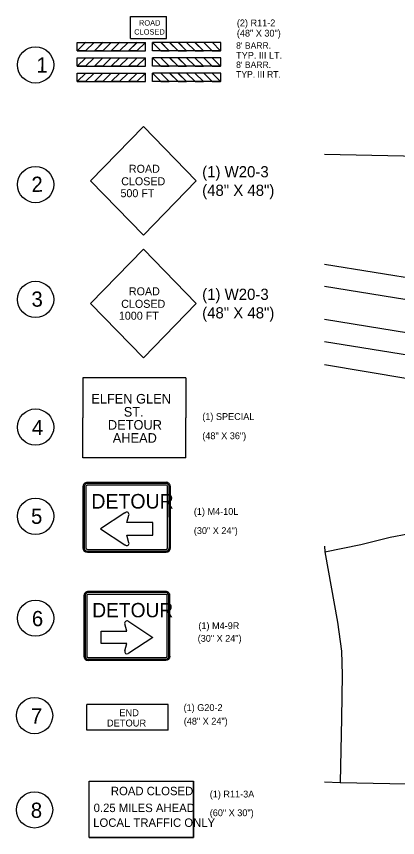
# Model space of a CAD drawing. Extents: x 185625 to 193575, y 1257500 to 1262681.
# Drawn here: x 185625 to 187128, y 1259342 to 1262581 of the extents above; entities that cross this region are included whole.
import ezdxf

# ---------------------------------------------------------------- set-up
doc = ezdxf.new("R2010")
doc.units = 0
for name, color, linetype in [('1', 7, 'Continuous'), ('10', 7, 'Continuous'), ('3', 7, 'Continuous'), ('8', 7, 'Continuous'), ('Level 42', 7, 'Continuous'), ('Level 8', 7, 'Continuous'), ('P_TC_Signs_Temporary', 7, 'Continuous')]:
    doc.layers.add(name, color=color, linetype=linetype)

msp = doc.modelspace()

# ---------------------------------------------------------------- linework, layer by layer
at = {"layer": '1'}
for p, q in [((185864.9, 1262445.4), (185898.6, 1262479.2)), ((185931.4, 1262479), (185897.9, 1262445.4)), ((185932.8, 1262445.4), (185966.6, 1262479.2)), ((185999.4, 1262479), (185965.8, 1262445.4)), ((185999.5, 1262445.4), (186033.2, 1262479.2)), ((186066, 1262479), (186032.5, 1262445.4)), ((186067.4, 1262445.4), (186101.1, 1262479.2)), ((186133.9, 1262479), (186100.4, 1262445.4)), ((186161.8, 1262479), (186195.3, 1262445.4)), ((186228.3, 1262445.4), (186194.6, 1262479.2)), ((186229.7, 1262479), (186263.3, 1262445.4)), ((186296.3, 1262445.4), (186262.6, 1262479.2)), ((186296.4, 1262479), (186329.9, 1262445.4)), ((186362.9, 1262445.4), (186329.2, 1262479.2)), ((186364.3, 1262479), (186397.8, 1262445.4)), ((186430.8, 1262445.4), (186397.1, 1262479.2)), ((185897.9, 1262445.4), (185864.9, 1262445.4)), ((185965.8, 1262445.4), (185932.8, 1262445.4)), ((186032.5, 1262445.4), (185999.5, 1262445.4)), ((186100.4, 1262445.4), (186067.4, 1262445.4)), ((186195.3, 1262445.4), (186228.3, 1262445.4)), ((186263.3, 1262445.4), (186296.3, 1262445.4)), ((186329.9, 1262445.4), (186362.9, 1262445.4)), ((186397.8, 1262445.4), (186430.8, 1262445.4)), ((185864.9, 1262384.8), (185898.6, 1262418.6)), ((185931.4, 1262418.4), (185897.9, 1262384.8)), ((185932.8, 1262384.8), (185966.6, 1262418.6)), ((185999.4, 1262418.4), (185965.8, 1262384.8)), ((185999.5, 1262384.8), (186033.2, 1262418.6)), ((186066, 1262418.4), (186032.5, 1262384.8)), ((186067.4, 1262384.8), (186101.1, 1262418.6)), ((186133.9, 1262418.4), (186100.4, 1262384.8)), ((186161.8, 1262418.4), (186195.3, 1262384.8)), ((186228.3, 1262384.8), (186194.6, 1262418.6)), ((186229.7, 1262418.4), (186263.3, 1262384.8)), ((186296.3, 1262384.8), (186262.6, 1262418.6)), ((186296.4, 1262418.4), (186329.9, 1262384.8)), ((186362.9, 1262384.8), (186329.2, 1262418.6)), ((186364.3, 1262418.4), (186397.8, 1262384.8)), ((186430.8, 1262384.8), (186397.1, 1262418.6)), ((185897.9, 1262384.8), (185864.9, 1262384.8)), ((185965.8, 1262384.8), (185932.8, 1262384.8)), ((186032.5, 1262384.8), (185999.5, 1262384.8)), ((186100.4, 1262384.8), (186067.4, 1262384.8)), ((186195.3, 1262384.8), (186228.3, 1262384.8)), ((186263.3, 1262384.8), (186296.3, 1262384.8)), ((186329.9, 1262384.8), (186362.9, 1262384.8)), ((186397.8, 1262384.8), (186430.8, 1262384.8)), ((185864.9, 1262324.2), (185898.6, 1262358)), ((185931.4, 1262357.8), (185897.9, 1262324.2)), ((185932.8, 1262324.2), (185966.6, 1262358)), ((185999.4, 1262357.8), (185965.8, 1262324.2)), ((185999.5, 1262324.2), (186033.2, 1262358)), ((186066, 1262357.8), (186032.5, 1262324.2)), ((186067.4, 1262324.2), (186101.1, 1262358)), ((186133.9, 1262357.8), (186100.4, 1262324.2)), ((186161.8, 1262357.8), (186195.3, 1262324.2)), ((186228.3, 1262324.2), (186194.6, 1262358)), ((186229.7, 1262357.8), (186263.3, 1262324.2)), ((186296.3, 1262324.2), (186262.6, 1262358)), ((186296.4, 1262357.8), (186329.9, 1262324.2)), ((186362.9, 1262324.2), (186329.2, 1262358)), ((186364.3, 1262357.8), (186397.8, 1262324.2)), ((186430.8, 1262324.2), (186397.1, 1262358)), ((185897.9, 1262324.2), (185864.9, 1262324.2)), ((185965.8, 1262324.2), (185932.8, 1262324.2)), ((186032.5, 1262324.2), (185999.5, 1262324.2)), ((186100.4, 1262324.2), (186067.4, 1262324.2)), ((186195.3, 1262324.2), (186228.3, 1262324.2)), ((186263.3, 1262324.2), (186296.3, 1262324.2)), ((186329.9, 1262324.2), (186362.9, 1262324.2)), ((186397.8, 1262324.2), (186430.8, 1262324.2)), ((186293, 1261155.8), (185887.4, 1261155.8)), ((185887.4, 1261155.8), (185887.4, 1260998.2)), ((186293, 1261155.8), (186293, 1260998.2)), ((185887.4, 1260840.5), (185887.4, 1260998.2)), ((186293, 1260840.5), (186293, 1260998.2)), ((186293, 1260840.5), (185887.4, 1260840.5))]:
    msp.add_line(p, q, dxfattribs=at)
msp.add_lwpolyline([(185912.2, 1259565.1), (186323.9, 1259565.1), (186323.9, 1259342.4), (185912.2, 1259342.4)], close=True, dxfattribs=at)
at = {"layer": '10'}
for points in [[(186840.7, 1262038.4), (188150.6, 1262010.8)], [(193575.5, 1260557.6), (193212.7, 1260596.5), (192742.7, 1260653.6), (192330.9, 1260716.5), (191888.1, 1260787.1), (191307.8, 1260876.8), (190478.8, 1261007.5), (190038.6, 1261084.8), (189048.5, 1261248.2), (187820.3, 1261444.8), (186840.7, 1261603.3)], [(186840.7, 1261517.2), (187806.8, 1261360.9), (189034.8, 1261164.3), (190024.3, 1261001), (190464.9, 1260923.6), (191294.7, 1260792.9), (191874.9, 1260703.1), (192317.8, 1260632.5), (192731.2, 1260569.4), (193203.1, 1260512.1), (193575.5, 1260472.1)], [(193575.5, 1260341.4), (193188.3, 1260382.9), (192713.5, 1260440.6), (192297.7, 1260504), (191854.7, 1260574.7), (191274.6, 1260664.4), (190443.5, 1260795.4), (190002.5, 1260872.9), (189014, 1261035.9), (187786.1, 1261232.6), (186840.7, 1261385.5)], [(186840.7, 1261299.4), (187772.6, 1261148.7), (189000.3, 1260952), (189988.2, 1260789.1), (190429.5, 1260711.5), (191261.5, 1260580.4), (191841.6, 1260490.7), (192284.6, 1260420), (192702, 1260356.4), (193178.6, 1260298.5), (193575.5, 1260255.9)], [(191582.4, 1259981.2), (191550.8, 1259987.2), (191524.3, 1260006.5), (191500.2, 1260059.6), (191471.2, 1260173), (191442.3, 1260243), (191410.9, 1260284), (191348.2, 1260337.1), (191275.8, 1260382.9), (191155.2, 1260424), (190983.1, 1260495.9), (190840.8, 1260546.5), (190511.6, 1260605.2), (189655.3, 1260749.8), (189036.5, 1260848.7), (188221.1, 1260983.9), (187505.6, 1261095.4), (186840.7, 1261207.7)], [(186840.7, 1260469.2), (186841.7, 1260469.4), (186983.7, 1260498.7), (187099, 1260527.9), (187168.8, 1260540.9)], [(186840.7, 1260491.3), (186841.7, 1260469.4), (186892.1, 1260192.5), (186906.7, 1260077.1), (186909.9, 1259984.5), (186906.7, 1259813.9), (186902, 1259559.2)], [(186840.7, 1259561.8), (186902, 1259559.2), (187228.5, 1259552.7), (187288.6, 1259565.3), (187338.9, 1259584.8), (187405.5, 1259610.8), (187459.1, 1259625.4), (187493.2, 1259631.9), (187552.1, 1259638.3), (187878.6, 1259630.2)]]:
    msp.add_lwpolyline(points, dxfattribs=at)
at = {"layer": '3'}
for p, q in [((186075.4, 1262493.8), (186075.4, 1262581.3)), ((186075.4, 1262581.3), (186217.6, 1262581.3)), ((186217.6, 1262493.8), (186217.6, 1262581.3)), ((185864.8, 1262479.1), (186134.1, 1262479.1)), ((185864.8, 1262445.3), (185864.8, 1262479.1)), ((185932.8, 1262445.4), (185966.4, 1262479)), ((185965.7, 1262445.4), (185999.5, 1262479.1)), ((185999.5, 1262445.4), (186033.3, 1262479.2)), ((186032.4, 1262445.3), (186066.1, 1262479)), ((186067.4, 1262445.4), (186101, 1262479)), ((186075.4, 1262493.8), (186217.6, 1262493.8)), ((186100.4, 1262445.4), (186134.1, 1262479.1)), ((186134.1, 1262445.3), (186134.1, 1262479.1)), ((186195.3, 1262445.4), (186161.6, 1262479.1)), ((186430.9, 1262479.1), (186161.6, 1262479.1)), ((186161.6, 1262445.3), (186161.6, 1262479.1)), ((186228.3, 1262445.4), (186194.7, 1262479)), ((186263.4, 1262445.3), (186229.6, 1262479)), ((186296.3, 1262445.4), (186262.5, 1262479.2)), ((186330, 1262445.4), (186296.3, 1262479.1)), ((186362.9, 1262445.4), (186329.4, 1262479)), ((186430.9, 1262445.3), (186430.9, 1262479.1)), ((185864.8, 1262445.3), (186134.1, 1262445.3)), ((186133.9, 1262445.4), (186134.1, 1262445.6)), ((186161.8, 1262445.4), (186161.6, 1262445.6)), ((186430.9, 1262445.3), (186161.6, 1262445.3)), ((185864.8, 1262418.5), (186134.1, 1262418.5)), ((185864.8, 1262384.7), (185864.8, 1262418.5)), ((185932.8, 1262384.8), (185966.4, 1262418.4)), ((185965.7, 1262384.8), (185999.5, 1262418.5)), ((185999.5, 1262384.8), (186033.3, 1262418.6)), ((186032.4, 1262384.7), (186066.1, 1262418.4)), ((186067.4, 1262384.8), (186101, 1262418.4)), ((186100.4, 1262384.8), (186134.1, 1262418.5)), ((186134.1, 1262384.7), (186134.1, 1262418.5)), ((186195.3, 1262384.8), (186161.6, 1262418.5)), ((186430.9, 1262418.5), (186161.6, 1262418.5)), ((186161.6, 1262384.7), (186161.6, 1262418.5)), ((186228.3, 1262384.8), (186194.7, 1262418.4)), ((186263.4, 1262384.7), (186229.6, 1262418.4)), ((186296.3, 1262384.8), (186262.5, 1262418.6)), ((186330, 1262384.8), (186296.3, 1262418.5)), ((186362.9, 1262384.8), (186329.4, 1262418.4)), ((186430.9, 1262384.7), (186430.9, 1262418.5)), ((185864.8, 1262384.7), (186134.1, 1262384.7)), ((186133.9, 1262384.8), (186134.1, 1262385)), ((186161.8, 1262384.8), (186161.6, 1262385)), ((186430.9, 1262384.7), (186161.6, 1262384.7)), ((185864.8, 1262357.9), (186134.1, 1262357.9)), ((185864.8, 1262324.1), (185864.8, 1262357.9)), ((185932.8, 1262324.2), (185966.4, 1262357.8)), ((185965.7, 1262324.2), (185999.5, 1262357.9)), ((185999.5, 1262324.2), (186033.3, 1262358)), ((186032.4, 1262324.1), (186066.1, 1262357.8)), ((186067.4, 1262324.2), (186101, 1262357.8)), ((186100.4, 1262324.2), (186134.1, 1262357.9)), ((186134.1, 1262324.1), (186134.1, 1262357.9)), ((186195.3, 1262324.2), (186161.6, 1262357.9)), ((186430.9, 1262357.9), (186161.6, 1262357.9)), ((186161.6, 1262324.1), (186161.6, 1262357.9)), ((186228.3, 1262324.2), (186194.7, 1262357.8)), ((186263.4, 1262324.1), (186229.6, 1262357.8)), ((186296.3, 1262324.2), (186262.5, 1262358)), ((186330, 1262324.2), (186296.3, 1262357.9)), ((186362.9, 1262324.2), (186329.4, 1262357.8)), ((186430.9, 1262324.1), (186430.9, 1262357.9)), ((185864.8, 1262324.1), (186134.1, 1262324.1)), ((186133.9, 1262324.2), (186134.1, 1262324.4)), ((186161.8, 1262324.2), (186161.6, 1262324.4)), ((186430.9, 1262324.1), (186161.6, 1262324.1)), ((185912.2, 1259565.1), (186323.9, 1259565.1)), ((185912.2, 1259342.4), (185912.2, 1259565.1)), ((186323.9, 1259342.4), (186323.9, 1259565.1)), ((185912.2, 1259342.4), (186323.9, 1259342.4))]:
    msp.add_line(p, q, dxfattribs=at)
at = {"layer": 'Level 42'}
for p, q in [((186224, 1259867.2), (185902.4, 1259867.2)), ((185902.4, 1259766.2), (185902.4, 1259867.2)), ((186224, 1259766.2), (186224, 1259867.2)), ((186224, 1259766.2), (185902.4, 1259766.2))]:
    msp.add_line(p, q, dxfattribs=at)
at = {"layer": 'Level 8'}
for p, q in [((186125.9, 1262146.9), (185917.5, 1261932.5)), ((186334.3, 1261932.5), (186125.9, 1262146.9)), ((186125.9, 1261718.4), (185917.5, 1261932.5)), ((186334.3, 1261932.5), (186125.9, 1261718.4)), ((186125.9, 1261663.5), (185917.5, 1261449.2)), ((186334.3, 1261449.2), (186125.9, 1261663.5)), ((186125.9, 1261235), (185917.5, 1261449.2)), ((186334.3, 1261449.2), (186125.9, 1261235))]:
    msp.add_line(p, q, dxfattribs=at)
for centre in [(185700.9, 1262389.9), (185701, 1261917.9), (185701, 1261465.2), (185701, 1260961.6), (185701, 1260609.6), (185701, 1260207.9), (185696.9, 1259823.6), (185696.8, 1259451.7)]:
    msp.add_circle(centre, 71.5, dxfattribs=at)
at = {"layer": 'P_TC_Signs_Temporary'}
for p, q in [((185887.7, 1260726.3), (185887.8, 1260484.9)), ((185892, 1260726.4), (185892.1, 1260484.9)), ((185899.2, 1260726.4), (185899.3, 1260484.9)), ((186215.3, 1260743.7), (185904.9, 1260743.6)), ((186215.3, 1260739.4), (185904.9, 1260739.3)), ((186215.3, 1260732.2), (185904.9, 1260732.1)), ((186221.2, 1260485.1), (186221.1, 1260726.5)), ((186228.4, 1260485.1), (186228.3, 1260726.5)), ((186232.7, 1260485.1), (186232.6, 1260726.5)), ((185905, 1260479.2), (186215.4, 1260479.3)), ((185905, 1260472), (186215.4, 1260472.1)), ((185905, 1260467.7), (186215.4, 1260467.8)), ((186214, 1260313.1), (185908.6, 1260313)), ((186214, 1260308.9), (185908.6, 1260308.7)), ((185891.6, 1260296), (185891.7, 1260058.5)), ((185895.9, 1260296), (185896, 1260058.5)), ((185902.9, 1260296), (185903, 1260058.5)), ((186214, 1260301.8), (185908.6, 1260301.7)), ((186219.7, 1260058.6), (186219.6, 1260296.1)), ((186226.8, 1260058.6), (186226.7, 1260296.1)), ((186231, 1260058.6), (186230.9, 1260296.1)), ((185908.7, 1260052.8), (186214.1, 1260053)), ((185908.7, 1260045.8), (186214.1, 1260045.9)), ((185908.7, 1260041.5), (186214.1, 1260041.7))]:
    msp.add_line(p, q, dxfattribs=at)
for points in [[(186053.1, 1260622.9), (185956.7, 1260559.7), (186053.1, 1260496.8)], [(186069, 1260505.4), (186060.2, 1260534.8), (186163.7, 1260534.8), (186163.6, 1260584.7), (186060.2, 1260584.7), (186069.1, 1260614.1)], [(186052.7, 1260078.6), (186061.4, 1260107.5), (185959.6, 1260107.5), (185959.5, 1260156.6), (186061.3, 1260156.6), (186052.5, 1260185.5)], [(186068.3, 1260194.2), (186163.1, 1260132.1), (186068.3, 1260070.2)]]:
    msp.add_lwpolyline(points, dxfattribs=at)
for centre, radius, start, end in [((185904.9, 1260726.4), 17.2, 90.0233, 180.0233), ((185904.9, 1260726.4), 12.9, 90.0233, 180.0233), ((185904.9, 1260726.4), 5.75, 90.0233, 180.0233), ((186215.3, 1260726.5), 17.2, 0.0233, 90.0233), ((186215.3, 1260726.5), 12.9, 0.0233, 90.0233), ((186215.3, 1260726.5), 5.75, 0.0233, 90.0233), ((185548.3, 1261392.7), 920.5, 303.2519, 303.4124), ((186060.3, 1260616.6), 9.2, 344.0542, 123.4124), ((186060.3, 1260502.9), 9.03, 236.7129, 15.9924), ((185905, 1260484.9), 17.2, 180.0233, 270.0233), ((185905, 1260484.9), 12.9, 180.0233, 270.0233), ((185905, 1260484.9), 5.75, 180.0233, 270.0233), ((185550.2, 1259725.8), 920.5, 56.7129, 56.8803), ((186215.4, 1260485.1), 12.9, 270.0233, 0.0233), ((186215.4, 1260485.1), 5.75, 270.0233, 0.0233), ((186215.4, 1260485.1), 17.2, 270.0233, 0.0233), ((185908.6, 1260296), 17, 90.0233, 180.0233), ((185908.6, 1260296), 12.7, 90.0233, 180.0233), ((186214, 1260296.1), 17, 0.0233, 90.0233), ((186214, 1260296.1), 12.7, 0.0233, 90.0233), ((185908.6, 1260296), 5.66, 90.0233, 180.0233), ((186214, 1260296.1), 5.66, 0.0233, 90.0233), ((186061.2, 1260188), 9.05, 56.6342, 195.9924), ((186564.3, 1260952), 905.7, 236.6342, 236.7947), ((186061.2, 1260076.1), 8.88, 164.0542, 303.3337), ((185908.7, 1260058.5), 17, 180.0233, 270.0233), ((185908.7, 1260058.5), 12.7, 180.0233, 270.0233), ((185908.7, 1260058.5), 5.66, 180.0233, 270.0233), ((186563.8, 1259312), 905.7, 123.1663, 123.3337), ((186214.1, 1260058.6), 12.7, 270.0233, 0.0233), ((186214.1, 1260058.6), 5.66, 270.0233, 0.0233), ((186214.1, 1260058.6), 17, 270.0233, 0.0233)]:
    msp.add_arc(centre, radius, start, end, dxfattribs=at)

# ---------------------------------------------------------------- texts
at = {"layer": '1'}
msp.add_text('0.25 MILES AHEAD', height=33.355, dxfattribs=at).set_placement((185929.9, 1259443))
at = {"layer": '3'}
for s, height, p in [('ROAD', 21.2, (186108.8, 1262545.1)), ('CLOSED', 21.31, (186089.7, 1262509.6)), ('ELFEN GLEN ', 37.762, (185920.5, 1261054.4)), ('ST.', 37.76, (186048.6, 1261002.9)), ('DETOUR ', 37.76, (185986.1, 1260951.4)), ('AHEAD', 37.76, (186005.2, 1260899.8)), ('ROAD CLOSED', 33.356, (185997.8, 1259509.5)), ('LOCAL TRAFFIC ONLY', 33.356, (185928.1, 1259384.7))]:
    msp.add_text(s, height=height, dxfattribs=at).set_placement(p)
at = {"layer": '8'}
for s, height, p in [('(2) R11-2', 26.85, (186494.7, 1262542.3)), ('(48" X 30")', 26.847, (186494.7, 1262501.8)), ("8' BARR.", 25.24, (186491.8, 1262453.8)), ('TYP. III LT.', 26.847, (186491.8, 1262414.4)), ("8' BARR.", 25.24, (186491.8, 1262378.1)), ('TYP. III RT.', 25.239, (186491.8, 1262340.3)), ('(1) R11-3A', 26.85, (186387.8, 1259500.6)), ('(60" X 30")', 26.847, (186387.8, 1259426.8))]:
    msp.add_text(s, height=height, dxfattribs=at).set_placement(p)
for s, height, p in [('(1) SPECIAL', 26.847, (186358.3, 1260989.7)), ('(48" X 36")', 26.847, (186358.3, 1260913.8)), ('(1) M4-10L', 26.85, (186325, 1260615.2)), ('(30" X 24")', 26.847, (186325, 1260539.7))]:
    msp.add_text(s, height=height, rotation=0.0007, dxfattribs=at).set_placement(p)
at = {"layer": 'Level 42'}
for s, p in [('END', (186030.9, 1259821)), ('DETOUR', (185982.1, 1259780.5))]:
    msp.add_text(s, height=27.45, rotation=0, dxfattribs=at).set_placement(p)
at = {"layer": 'Level 8'}
for s, height, rotation, p in [('1', 60, 359.6134, (185703.9, 1262359.8)), ('ROAD', 31.58, 0.0006, (186068.9, 1261964.6)), ('2', 60, 1.5816, (185685.6, 1261888.6)), ('CLOSED', 31.58, 0.0005, (186038.6, 1261915.3)), ('500 FT', 31.58, 0.0006, (186035.7, 1261868.3)), ('ROAD', 31.58, 0.0006, (186068.9, 1261481.3)), ('3', 60, 1.5816, (185685.5, 1261435.8)), ('CLOSED', 31.58, 0.0005, (186038.6, 1261431.9)), ('1000 FT', 31.58, 0.0006, (186029.4, 1261385)), ('4', 60, 359.6134, (185686.1, 1260930.2)), ('5', 60, 359.6134, (185682.8, 1260580)), ('6', 60, 359.6134, (185686.1, 1260176.5)), ('(1) M4-9R', 26.85, 0.0007, (186343, 1260164.6)), ('(30" X 24")', 26.847, 0.0007, (186340.2, 1260114.7)), ('7', 60, 359.6134, (185682, 1259792.2)), ('(1) G20-2', 26.85, 0, (186284.6, 1259841.7)), ('(48" X 24")', 26.847, 0, (186285.3, 1259788)), ('8', 60, 359.6134, (185681.9, 1259420.3))]:
    msp.add_text(s, height=height, rotation=rotation, dxfattribs=at).set_placement(p)
for s, height, p in [('(1) W20-3', 44.13, (186357.9, 1261946.6)), ('(48" X 48")', 44.126, (186357.9, 1261873.5)), ('(1) W20-3', 44.13, (186357.9, 1261463.2)), ('(48" X 48")', 44.126, (186357.9, 1261390.1))]:
    msp.add_text(s, height=height, dxfattribs=at).set_placement(p)
at = {"layer": 'P_TC_Signs_Temporary'}
for height, p in [(57.48, (185921, 1260640.1)), (56.55, (185924.4, 1260211.2))]:
    msp.add_text('DETOUR', height=height, rotation=0.0233, dxfattribs=at).set_placement(p)

doc.saveas('drawing.dxf')
